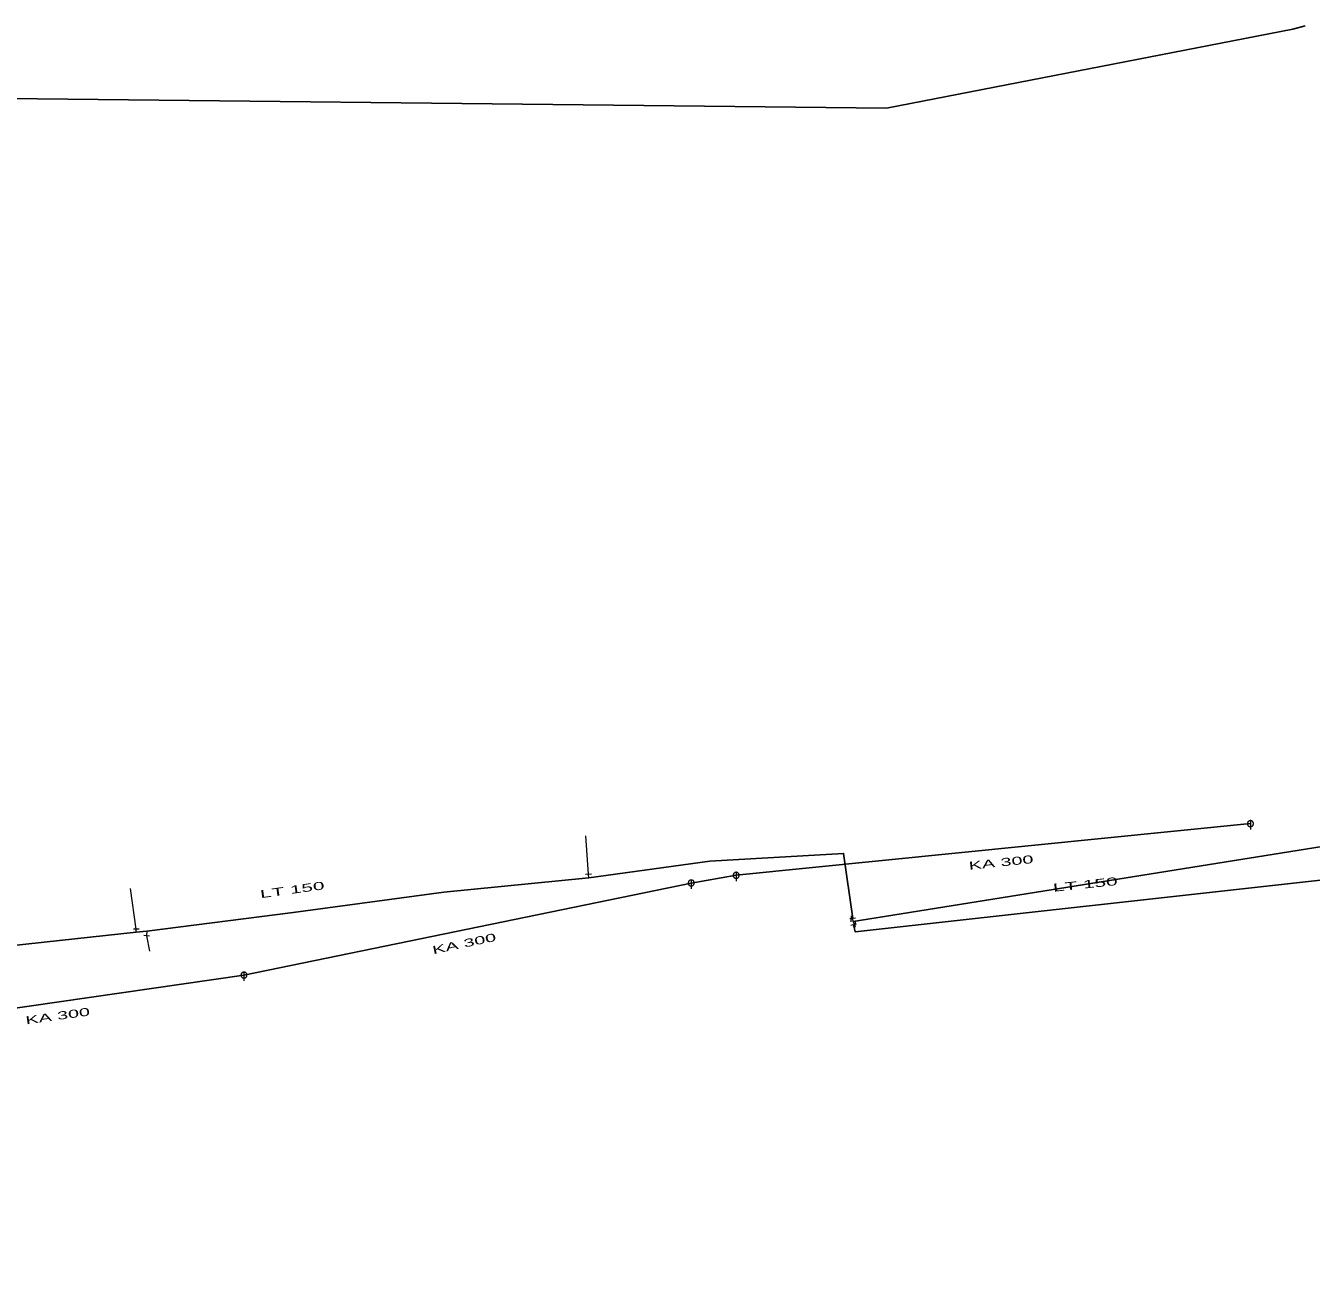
# Model space of a CAD drawing. Extents: x -687515 to -686506, y -974029 to -973461.
# Drawn here: x -686751.9 to -686644.8, y -973569.2 to -973464.5 of the extents above; entities that cross this region are included whole.
import ezdxf
from ezdxf.enums import TextEntityAlignment as Align

# ---------------------------------------------------------------- set-up
doc = ezdxf.new("R2010")
doc.units = 0
doc.header["$LTSCALE"] = 0.27
for name, color, linetype, lineweight in [('1', 7, 'Continuous', 13), ('13', 7, 'Continuous', 13), ('14', 7, 'Continuous', 25), ('17', 7, 'Continuous', 25), ('22', 7, 'Continuous', 13), ('34', 7, 'Continuous', 13), ('47', 7, 'Continuous', 13)]:
    doc.layers.add(name, color=color, linetype=linetype, lineweight=lineweight)

msp = doc.modelspace()

# ---------------------------------------------------------------- linework, layer by layer
at = {"layer": '13'}
for p, q in [((-686705.019, -973535.15), (-686705.23, -973531.969)), ((-686742.7, -973539.74), (-686743.17, -973536.35)), ((-686741.839, -973540.289), (-686741.609, -973541.559))]:
    msp.add_line(p, q, dxfattribs=at)
at = {"layer": '14'}
for p, q in [((-686649.861, -973530.945), (-686692.714, -973535.249)), ((-686696.46, -973535.891), (-686733.729, -973543.563)), ((-686692.714, -973535.249), (-686696.46, -973535.891)), ((-686733.729, -973543.563), (-686765.07, -973548.078))]:
    msp.add_line(p, q, dxfattribs=at)
at = {"layer": '14', "lineweight": 13}
for p, q in [((-686705, -973535.449), (-686705.019, -973535.15)), ((-686682.969, -973539.099), (-686683.004, -973538.854)), ((-686742.7, -973539.99), (-686742.7, -973539.74)), ((-686741.809, -973539.91), (-686741.839, -973540.289))]:
    msp.add_line(p, q, dxfattribs=at)
at = {"layer": '17'}
for points in [[(-686645.309, -973464.46), (-686646.34, -973464.75), (-686680.188, -973471.317), (-686771.188, -973470.317), (-686761.188, -973557.317), (-686894.188, -973571.317), (-686953.188, -973578.317), (-686955.188, -973554.317), (-687116.188, -973577.317), (-687229.188, -973601.317), (-687468.188, -973649.317), (-687458.188, -973700.317)], [(-686636.679, -973468.495), (-686633.456, -973531.184), (-686682.969, -973539.099)], [(-686683.004, -973538.854), (-686683.77, -973533.43), (-686694.92, -973534.07), (-686705, -973535.449), (-686717.079, -973536.649), (-686729.629, -973538.359), (-686741.809, -973539.91), (-686742.699, -973539.989), (-686758.309, -973541.69), (-686758.27, -973542.34), (-686759.73, -973542.469), (-686769.002, -973543.42)], [(-686682.93, -973539.35), (-686682.8, -973539.949), (-686644.02, -973535.649), (-686638.37, -973534.82)]]:
    msp.add_lwpolyline(points, dxfattribs=at)
at = {"layer": '22'}
for p, q in [((-686649.86, -973530.693), (-686649.861, -973531.436)), ((-686696.459, -973535.639), (-686696.46, -973536.382)), ((-686692.713, -973534.997), (-686692.714, -973535.74)), ((-686733.728, -973543.311), (-686733.729, -973544.054))]:
    msp.add_line(p, q, dxfattribs=at)
for points in [[(-686649.609, -973530.945), (-686649.61, -973530.919), (-686649.614, -973530.893), (-686649.62, -973530.867), (-686649.63, -973530.843), (-686649.642, -973530.819), (-686649.656, -973530.797), (-686649.673, -973530.776), (-686649.691, -973530.758), (-686649.712, -973530.741), (-686649.734, -973530.727), (-686649.758, -973530.715), (-686649.782, -973530.705), (-686649.808, -973530.699), (-686649.834, -973530.695), (-686649.86, -973530.693), (-686649.886, -973530.694), (-686649.912, -973530.698), (-686649.938, -973530.704), (-686649.963, -973530.714), (-686649.986, -973530.726), (-686650.008, -973530.74), (-686650.029, -973530.757), (-686650.047, -973530.775), (-686650.064, -973530.796), (-686650.078, -973530.818), (-686650.09, -973530.842), (-686650.1, -973530.866), (-686650.107, -973530.892), (-686650.111, -973530.918), (-686650.113, -973530.944), (-686650.112, -973530.97), (-686650.108, -973530.996), (-686650.101, -973531.022), (-686650.091, -973531.047), (-686650.079, -973531.07), (-686650.065, -973531.092), (-686650.048, -973531.113), (-686650.03, -973531.131), (-686650.009, -973531.148), (-686649.987, -973531.162), (-686649.964, -973531.174), (-686649.939, -973531.184), (-686649.913, -973531.191), (-686649.887, -973531.195), (-686649.861, -973531.196), (-686649.835, -973531.196), (-686649.809, -973531.192), (-686649.783, -973531.185), (-686649.759, -973531.175), (-686649.735, -973531.163), (-686649.713, -973531.149), (-686649.692, -973531.132), (-686649.674, -973531.114), (-686649.657, -973531.093), (-686649.643, -973531.071), (-686649.631, -973531.048), (-686649.621, -973531.023), (-686649.615, -973530.997), (-686649.611, -973530.971)], [(-686696.208, -973535.891), (-686696.209, -973535.865), (-686696.213, -973535.839), (-686696.219, -973535.813), (-686696.229, -973535.789), (-686696.241, -973535.765), (-686696.255, -973535.743), (-686696.272, -973535.722), (-686696.29, -973535.704), (-686696.311, -973535.687), (-686696.333, -973535.673), (-686696.357, -973535.661), (-686696.381, -973535.651), (-686696.407, -973535.645), (-686696.433, -973535.641), (-686696.459, -973535.639), (-686696.485, -973535.64), (-686696.511, -973535.644), (-686696.537, -973535.65), (-686696.562, -973535.66), (-686696.585, -973535.672), (-686696.607, -973535.686), (-686696.628, -973535.703), (-686696.646, -973535.721), (-686696.663, -973535.742), (-686696.677, -973535.764), (-686696.689, -973535.788), (-686696.699, -973535.812), (-686696.706, -973535.838), (-686696.71, -973535.864), (-686696.712, -973535.89), (-686696.711, -973535.916), (-686696.707, -973535.942), (-686696.7, -973535.968), (-686696.69, -973535.993), (-686696.678, -973536.016), (-686696.664, -973536.038), (-686696.647, -973536.059), (-686696.629, -973536.077), (-686696.608, -973536.094), (-686696.586, -973536.108), (-686696.563, -973536.12), (-686696.538, -973536.13), (-686696.512, -973536.137), (-686696.486, -973536.141), (-686696.46, -973536.142), (-686696.434, -973536.142), (-686696.408, -973536.138), (-686696.382, -973536.131), (-686696.358, -973536.121), (-686696.334, -973536.109), (-686696.312, -973536.095), (-686696.291, -973536.078), (-686696.273, -973536.06), (-686696.256, -973536.039), (-686696.242, -973536.017), (-686696.23, -973535.994), (-686696.22, -973535.969), (-686696.214, -973535.943), (-686696.21, -973535.917)], [(-686692.462, -973535.249), (-686692.463, -973535.223), (-686692.467, -973535.197), (-686692.473, -973535.171), (-686692.483, -973535.147), (-686692.495, -973535.123), (-686692.509, -973535.101), (-686692.526, -973535.08), (-686692.544, -973535.062), (-686692.565, -973535.045), (-686692.587, -973535.031), (-686692.611, -973535.019), (-686692.635, -973535.009), (-686692.661, -973535.003), (-686692.687, -973534.999), (-686692.713, -973534.997), (-686692.739, -973534.998), (-686692.765, -973535.002), (-686692.791, -973535.008), (-686692.816, -973535.018), (-686692.839, -973535.03), (-686692.861, -973535.044), (-686692.882, -973535.061), (-686692.9, -973535.079), (-686692.917, -973535.1), (-686692.931, -973535.122), (-686692.943, -973535.146), (-686692.953, -973535.17), (-686692.96, -973535.196), (-686692.964, -973535.222), (-686692.966, -973535.248), (-686692.965, -973535.274), (-686692.961, -973535.3), (-686692.954, -973535.326), (-686692.944, -973535.351), (-686692.932, -973535.374), (-686692.918, -973535.396), (-686692.901, -973535.417), (-686692.883, -973535.435), (-686692.862, -973535.452), (-686692.84, -973535.466), (-686692.817, -973535.478), (-686692.792, -973535.488), (-686692.766, -973535.495), (-686692.74, -973535.499), (-686692.714, -973535.5), (-686692.688, -973535.5), (-686692.662, -973535.496), (-686692.636, -973535.489), (-686692.612, -973535.479), (-686692.588, -973535.467), (-686692.566, -973535.453), (-686692.545, -973535.436), (-686692.527, -973535.418), (-686692.51, -973535.397), (-686692.496, -973535.375), (-686692.484, -973535.352), (-686692.474, -973535.327), (-686692.468, -973535.301), (-686692.464, -973535.275)], [(-686733.477, -973543.563), (-686733.478, -973543.537), (-686733.482, -973543.511), (-686733.488, -973543.485), (-686733.498, -973543.461), (-686733.51, -973543.437), (-686733.524, -973543.415), (-686733.541, -973543.394), (-686733.559, -973543.376), (-686733.58, -973543.359), (-686733.602, -973543.345), (-686733.626, -973543.333), (-686733.65, -973543.323), (-686733.676, -973543.317), (-686733.702, -973543.313), (-686733.728, -973543.311), (-686733.754, -973543.312), (-686733.78, -973543.316), (-686733.806, -973543.322), (-686733.831, -973543.332), (-686733.854, -973543.344), (-686733.876, -973543.358), (-686733.897, -973543.375), (-686733.915, -973543.393), (-686733.932, -973543.414), (-686733.946, -973543.436), (-686733.958, -973543.46), (-686733.968, -973543.484), (-686733.975, -973543.51), (-686733.979, -973543.536), (-686733.981, -973543.562), (-686733.98, -973543.588), (-686733.976, -973543.614), (-686733.969, -973543.64), (-686733.959, -973543.665), (-686733.947, -973543.688), (-686733.933, -973543.71), (-686733.916, -973543.731), (-686733.898, -973543.749), (-686733.877, -973543.766), (-686733.855, -973543.78), (-686733.832, -973543.792), (-686733.807, -973543.802), (-686733.781, -973543.809), (-686733.755, -973543.813), (-686733.729, -973543.815), (-686733.703, -973543.814), (-686733.677, -973543.81), (-686733.651, -973543.803), (-686733.627, -973543.793), (-686733.603, -973543.781), (-686733.581, -973543.767), (-686733.56, -973543.75), (-686733.542, -973543.732), (-686733.525, -973543.711), (-686733.511, -973543.689), (-686733.499, -973543.666), (-686733.489, -973543.641), (-686733.483, -973543.615), (-686733.479, -973543.589)]]:
    msp.add_lwpolyline(points, close=True, dxfattribs=at)
at = {"layer": '34'}
for p, q in [((-686705.266, -973535.166), (-686704.771, -973535.133)), ((-686682.758, -973538.819), (-686683.249, -973538.888)), ((-686742.451, -973539.739), (-686742.947, -973539.738)), ((-686741.591, -973540.308), (-686742.086, -973540.269)), ((-686683.172, -973539.402), (-686682.687, -973539.297))]:
    msp.add_line(p, q, dxfattribs=at)
at = {"layer": '47'}
msp.add_line((-686683.144, -973538.62), (-686683.167, -973539.13), dxfattribs=at)
msp.add_lwpolyline([(-686683.144, -973538.62), (-686682.793, -973539.577), (-686682.77, -973539.067)], dxfattribs=at)

# ---------------------------------------------------------------- texts
at = {"layer": '1'}
for s, rotation, width, p in [('KA 300', 6, 1.85, (-686670.606, -973534.505)), ('LT 150', 8, 1.95, (-686729.661, -973536.781)), ('LT 150', 6, 1.95, (-686663.591, -973536.336)), ('KA 300', 12, 1.85, (-686715.309, -973541.262)), ('KA 300', 8, 1.85, (-686749.204, -973547.296))]:
    msp.add_text(s, height=0.6667, rotation=rotation, dxfattribs=dict(at, width=width)).set_placement(p, align=Align.CENTER)

doc.saveas('drawing.dxf')
